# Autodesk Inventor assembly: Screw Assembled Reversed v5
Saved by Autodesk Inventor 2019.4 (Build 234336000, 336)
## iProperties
Created: 2020-06
Part Number: Screw Assembled Reversed v5
Document SubType Name: Assembly
Designer: Administrator
Title: Screw Assembled Reversed v5
Author: Administrator
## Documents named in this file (26)
- c:\worker\convert-fusion-r04\tmp\job-1\85\output\files\12fc5e84-6763-4458-a53a-9d1ae2180744\Screw Assembled Reversed v5.iam
- c:\worker\convert-fusion-r04\tmp\job-1\85\output\files\12fc5e84-6763-4458-a53a-9d1ae2180744\Upgraded Screw Harry Edited v15(Mirror).ipt
- c:\worker\convert-fusion-r04\tmp\job-1\85\output\files\12fc5e84-6763-4458-a53a-9d1ae2180744\001 Roller v3(Mirror).ipt
- c:\worker\convert-fusion-r04\tmp\job-1\85\output\files\12fc5e84-6763-4458-a53a-9d1ae2180744\001 Roller v3(Mirror) (1).ipt
- c:\worker\convert-fusion-r04\tmp\job-1\85\output\files\12fc5e84-6763-4458-a53a-9d1ae2180744\001 Roller v3(Mirror) (2).ipt
- c:\worker\convert-fusion-r04\tmp\job-1\85\output\files\12fc5e84-6763-4458-a53a-9d1ae2180744\001 Roller v3(Mirror) (3).ipt
- c:\worker\convert-fusion-r04\tmp\job-1\85\output\files\12fc5e84-6763-4458-a53a-9d1ae2180744\001 Roller v3(Mirror) (4).ipt
- c:\worker\convert-fusion-r04\tmp\job-1\85\output\files\12fc5e84-6763-4458-a53a-9d1ae2180744\001 Roller v3(Mirror) (5).ipt
- c:\worker\convert-fusion-r04\tmp\job-1\85\output\files\12fc5e84-6763-4458-a53a-9d1ae2180744\001 Roller v3(Mirror) (6).ipt
- c:\worker\convert-fusion-r04\tmp\job-1\85\output\files\12fc5e84-6763-4458-a53a-9d1ae2180744\001 Roller v3(Mirror) (7).ipt
- c:\worker\convert-fusion-r04\tmp\job-1\85\output\files\12fc5e84-6763-4458-a53a-9d1ae2180744\001 Roller v3(Mirror) (8).ipt
- c:\worker\convert-fusion-r04\tmp\job-1\85\output\files\12fc5e84-6763-4458-a53a-9d1ae2180744\001 Roller v3(Mirror) (9).ipt
- c:\worker\convert-fusion-r04\tmp\job-1\85\output\files\12fc5e84-6763-4458-a53a-9d1ae2180744\001 Roller v3(Mirror) (10).ipt
- c:\worker\convert-fusion-r04\tmp\job-1\85\output\files\12fc5e84-6763-4458-a53a-9d1ae2180744\001 Roller v3(Mirror) (11).ipt
- c:\worker\convert-fusion-r04\tmp\job-1\85\output\files\12fc5e84-6763-4458-a53a-9d1ae2180744\Component1(Mirror).ipt
- c:\worker\convert-fusion-r04\tmp\job-1\85\output\files\12fc5e84-6763-4458-a53a-9d1ae2180744\Component10(Mirror).ipt
- c:\worker\convert-fusion-r04\tmp\job-1\85\output\files\12fc5e84-6763-4458-a53a-9d1ae2180744\Component2(Mirror).ipt
- c:\worker\convert-fusion-r04\tmp\job-1\85\output\files\12fc5e84-6763-4458-a53a-9d1ae2180744\Component12(Mirror).ipt
- c:\worker\convert-fusion-r04\tmp\job-1\85\output\files\12fc5e84-6763-4458-a53a-9d1ae2180744\Component6(Mirror).ipt
- c:\worker\convert-fusion-r04\tmp\job-1\85\output\files\12fc5e84-6763-4458-a53a-9d1ae2180744\Component3(Mirror).ipt
- c:\worker\convert-fusion-r04\tmp\job-1\85\output\files\12fc5e84-6763-4458-a53a-9d1ae2180744\Component7(Mirror).ipt
- c:\worker\convert-fusion-r04\tmp\job-1\85\output\files\12fc5e84-6763-4458-a53a-9d1ae2180744\Component8(Mirror).ipt
- c:\worker\convert-fusion-r04\tmp\job-1\85\output\files\12fc5e84-6763-4458-a53a-9d1ae2180744\Component11(Mirror).ipt
- c:\worker\convert-fusion-r04\tmp\job-1\85\output\files\12fc5e84-6763-4458-a53a-9d1ae2180744\Component4(Mirror).ipt
- c:\worker\convert-fusion-r04\tmp\job-1\85\output\files\12fc5e84-6763-4458-a53a-9d1ae2180744\Component5(Mirror).ipt
- c:\worker\convert-fusion-r04\tmp\job-1\85\output\files\12fc5e84-6763-4458-a53a-9d1ae2180744\Component9(Mirror).ipt
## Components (25 placed, 25 different names)
1. Upgraded Screw Harry Edited v15(Mirror):1
2. 001 Roller v3(Mirror):1
3. 001 Roller v3(Mirror) (1):1
4. 001 Roller v3(Mirror) (2):1
5. 001 Roller v3(Mirror) (3):1
6. 001 Roller v3(Mirror) (4):1
7. 001 Roller v3(Mirror) (5):1
8. 001 Roller v3(Mirror) (6):1
9. 001 Roller v3(Mirror) (7):1
10. 001 Roller v3(Mirror) (8):1
11. 001 Roller v3(Mirror) (9):1
12. 001 Roller v3(Mirror) (10):1
13. 001 Roller v3(Mirror) (11):1
14. Component1(Mirror):1
15. Component10(Mirror):1
16. Component2(Mirror):1
17. Component12(Mirror):1
18. Component6(Mirror):1
19. Component3(Mirror):1
20. Component7(Mirror):1
21. Component8(Mirror):1
22. Component11(Mirror):1
23. Component4(Mirror):1
24. Component5(Mirror):1
25. Component9(Mirror):1
